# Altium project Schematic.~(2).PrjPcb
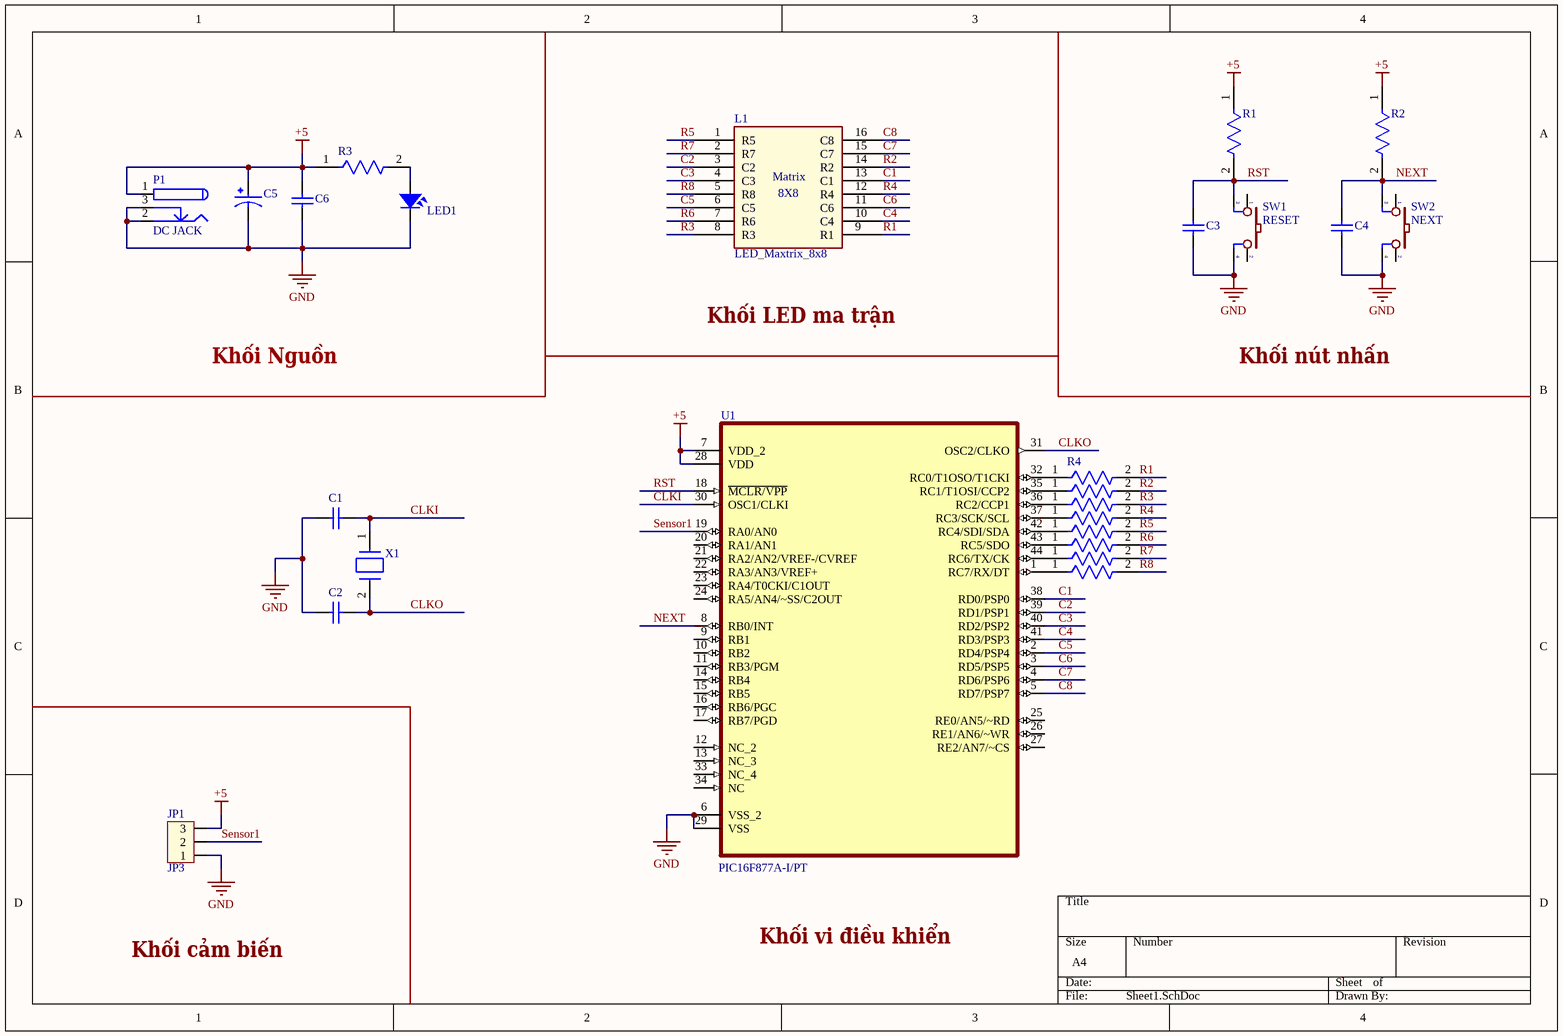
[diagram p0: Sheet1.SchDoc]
1 sheet, 25 parts. Net scope: global (net labels, ports and power ports of the same name join across sheets).

## Sheet Sheet1.SchDoc
size A4; SheetNumber: 1; SheetTotal: 1

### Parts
C1  22p  [CAPC2013X94X50LL25T25]  (value not drawn)
C2  22p  [CAPC2013X94X50LL25T25]  (value not drawn)
C3  0.1uF  [CAPC2013X94X50LL25T25]  (value not drawn)
C4  0.1uF  [CAPC2013X94X50LL25T25]  (value not drawn)
C5  EEE-FK1H101GP  [FP-FKF-MFG]  (value not drawn)
C6  0.1uF  [CAPC2013X94X50LL25T25]  (value not drawn)
JP1  JP3  [CON3]
L1  LED_Maxtrix_8x8  [LED_Matrix_8x8]
LED1  LED SMD  [SM-LED-0805-Green]  (value not drawn)
P1  DC JACK  [DC5.5/2.1]
R1  10k  [FP-CR0805-MFG]  (value not drawn)
R2  10k  [FP-CR0805-MFG]  (value not drawn)
R3  470R  [FP-CR0805-IPC_A]  (value not drawn)
R4  330R  [FP-CR0805-IPC_A]  (value not drawn)
R5  330R  [FP-CR0805-IPC_A]  (value not drawn)
R6  330R  [FP-CR0805-IPC_A]  (value not drawn)
R7  330R  [FP-CR0805-IPC_A]  (value not drawn)
R8  330R  [FP-CR0805-IPC_A]  (value not drawn)
R9  330R  [FP-CR0805-IPC_A]  (value not drawn)
R10  330R  [FP-CR0805-IPC_A]  (value not drawn)
R11  330R  [FP-CR0805-IPC_A]  (value not drawn)
SW1  RESET  [SW4]
SW2  NEXT  [SW4]
U1  PIC16F877A-I/PT  [TQFP-44]
X1  16MHz  [FP-ABM7-MFG]  (value not drawn)

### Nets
+5: C5.1 C6.2 JP1.3 P1.1 R1.1 R2.1 R3.1 U1.7(VDD_2) U1.28(VDD)
GND: C1.1 C2.1 C3.1 C4.1 C5.2 C6.1 JP1.1 LED1.2 P1.2 P1.3 SW1.4 SW2.4 U1.6(VSS_2) U1.29(VSS)
C1: L1.13(C1) U1.38(RD0/PSP0)
C2: L1.3(C2) U1.39(RD1/PSP1)
C3: L1.4(C3) U1.40(RD2/PSP2)
C4: L1.10(C4) U1.41(RD3/PSP3)
C5: L1.6(C5) U1.2(RD4/PSP4)
C6: L1.11(C6) U1.3(RD5/PSP5)
C7: L1.15(C7) U1.4(RD6/PSP6)
C8: L1.16(C8) U1.5(RD7/PSP7)
CLKI: C1.2 U1.30(OSC1/CLKI) X1.1
CLKO: C2.2 U1.31(OSC2/CLKO) X1.2
NEXT: C4.2 R2.2 SW2.3 U1.8(RB0/INT)
R1: L1.9(R1) R4.2
R2: L1.14(R2) R5.2
R3: L1.8(R3) R6.2
R4: L1.12(R4) R7.2
R5: L1.1(R5) R8.2
R6: L1.7(R6) R9.2
R7: L1.2(R7) R10.2
R8: L1.5(R8) R11.2
RST: C3.2 R1.2 SW1.3 U1.18(~{MCLR/VPP})
Sensor1: JP1.2 U1.19(RA0/AN0)
NetLED1_1: LED1.1 R3.2
NetR4_1: R4.1 U1.32(RC0/T1OSO/T1CKI)
NetR5_1: R5.1 U1.35(RC1/T1OSI/CCP2)
NetR6_1: R6.1 U1.36(RC2/CCP1)
NetR7_1: R7.1 U1.37(RC3/SCK/SCL)
NetR8_1: R8.1 U1.42(RC4/SDI/SDA)
NetR9_1: R9.1 U1.43(RC5/SDO)
NetR10_1: R10.1 U1.44(RC6/TX/CK)
NetR11_1: R11.1 U1.1(RC7/RX/DT)

Not connected (* = marked no-connect by the designer): SW1 1 2; SW2 1 2; U1 9(RB1) 10(RB2) 11(RB3/PGM) 12(NC_2) 13(NC_3) 14(RB4) 15(RB5) 16(RB6/PGC) 17(RB7/PGD) 20(RA1/AN1) 21(RA2/AN2/VREF-/CVREF) 22(RA3/AN3/VREF+) 23(RA4/T0CKI/C1OUT) 24(RA5/AN4/~SS/C2OUT) 25(RE0/AN5/~RD) 26(RE1/AN6/~WR) 27(RE2/AN7/~CS) 33(NC_4) 34(NC)

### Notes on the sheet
- Khối Nguồn
- Labels drawn without touching a wire or pin: Khối cảm biến, Khối LED ma trận, Khối nút nhấn, Khối vi điều khiển

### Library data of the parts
C1-C4 C6 = LD051C104KAB2A: Cap Ceramic 0.1uF 100V X7R 10% SMD 0805 125°C Embossed T/R; Manufacturer: Kyocera AVX; Value: 100nF
C5 = EEE-FK1H101GP: Cap Aluminum 100uF 50V 20% (8 X 10.2mm) SMD 350mA 5000 hr 105°C T/R; Manufacturer: Panasonic; Life (Hours): 5000Hour; Leakage Current: 10mA; Impedance: 340mR
JP1 = Con3: Connector 3
LED1 = LED-SMD-0805
P1 = DC5.5/2.1: Low Voltage Power Supply Connector; Solder: WAVE
R1-R3 = CR0805-JW-331ELF: Res Thick Film 0805 330 Ohm 5% 1/8W ±200ppm/°C Molded SMD SMD Paper Tape on Plastic Reel; Manufacturer: Bourns; Value: 330R; Power Rating: 125mW; Voltage Rating: 150V
R4-R11 = CR0805-JW-331ELF: Res Thick Film 0805 330 Ohm 5% 1/8W ±200ppm/°C Molded SMD SMD Paper Tape on Plastic Reel; Manufacturer: Bourns; Power Rating: 125mW; Voltage Rating: 150V
SW1 SW2 = SW4-1: Switch button 4 pin; Value: SW chip 4 pin
U1 = PIC16F877A-I/PT: PIC16F877A Microcontroller IC 8-Bit 20MHz 14KB _8K x 14_ FLASH 44-TQFP _10x10_; MF: Microchip
X1 = ABM7-16.000MHZ-4-T: Crystal 16MHz ±30ppm (Tol) ±50ppm (Stability) 18pF FUND 50Ohm 2-Pin Mini-CSMD T/R; Manufacturer: Abracon; ESR (Equivalent Series Resistance): 50R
